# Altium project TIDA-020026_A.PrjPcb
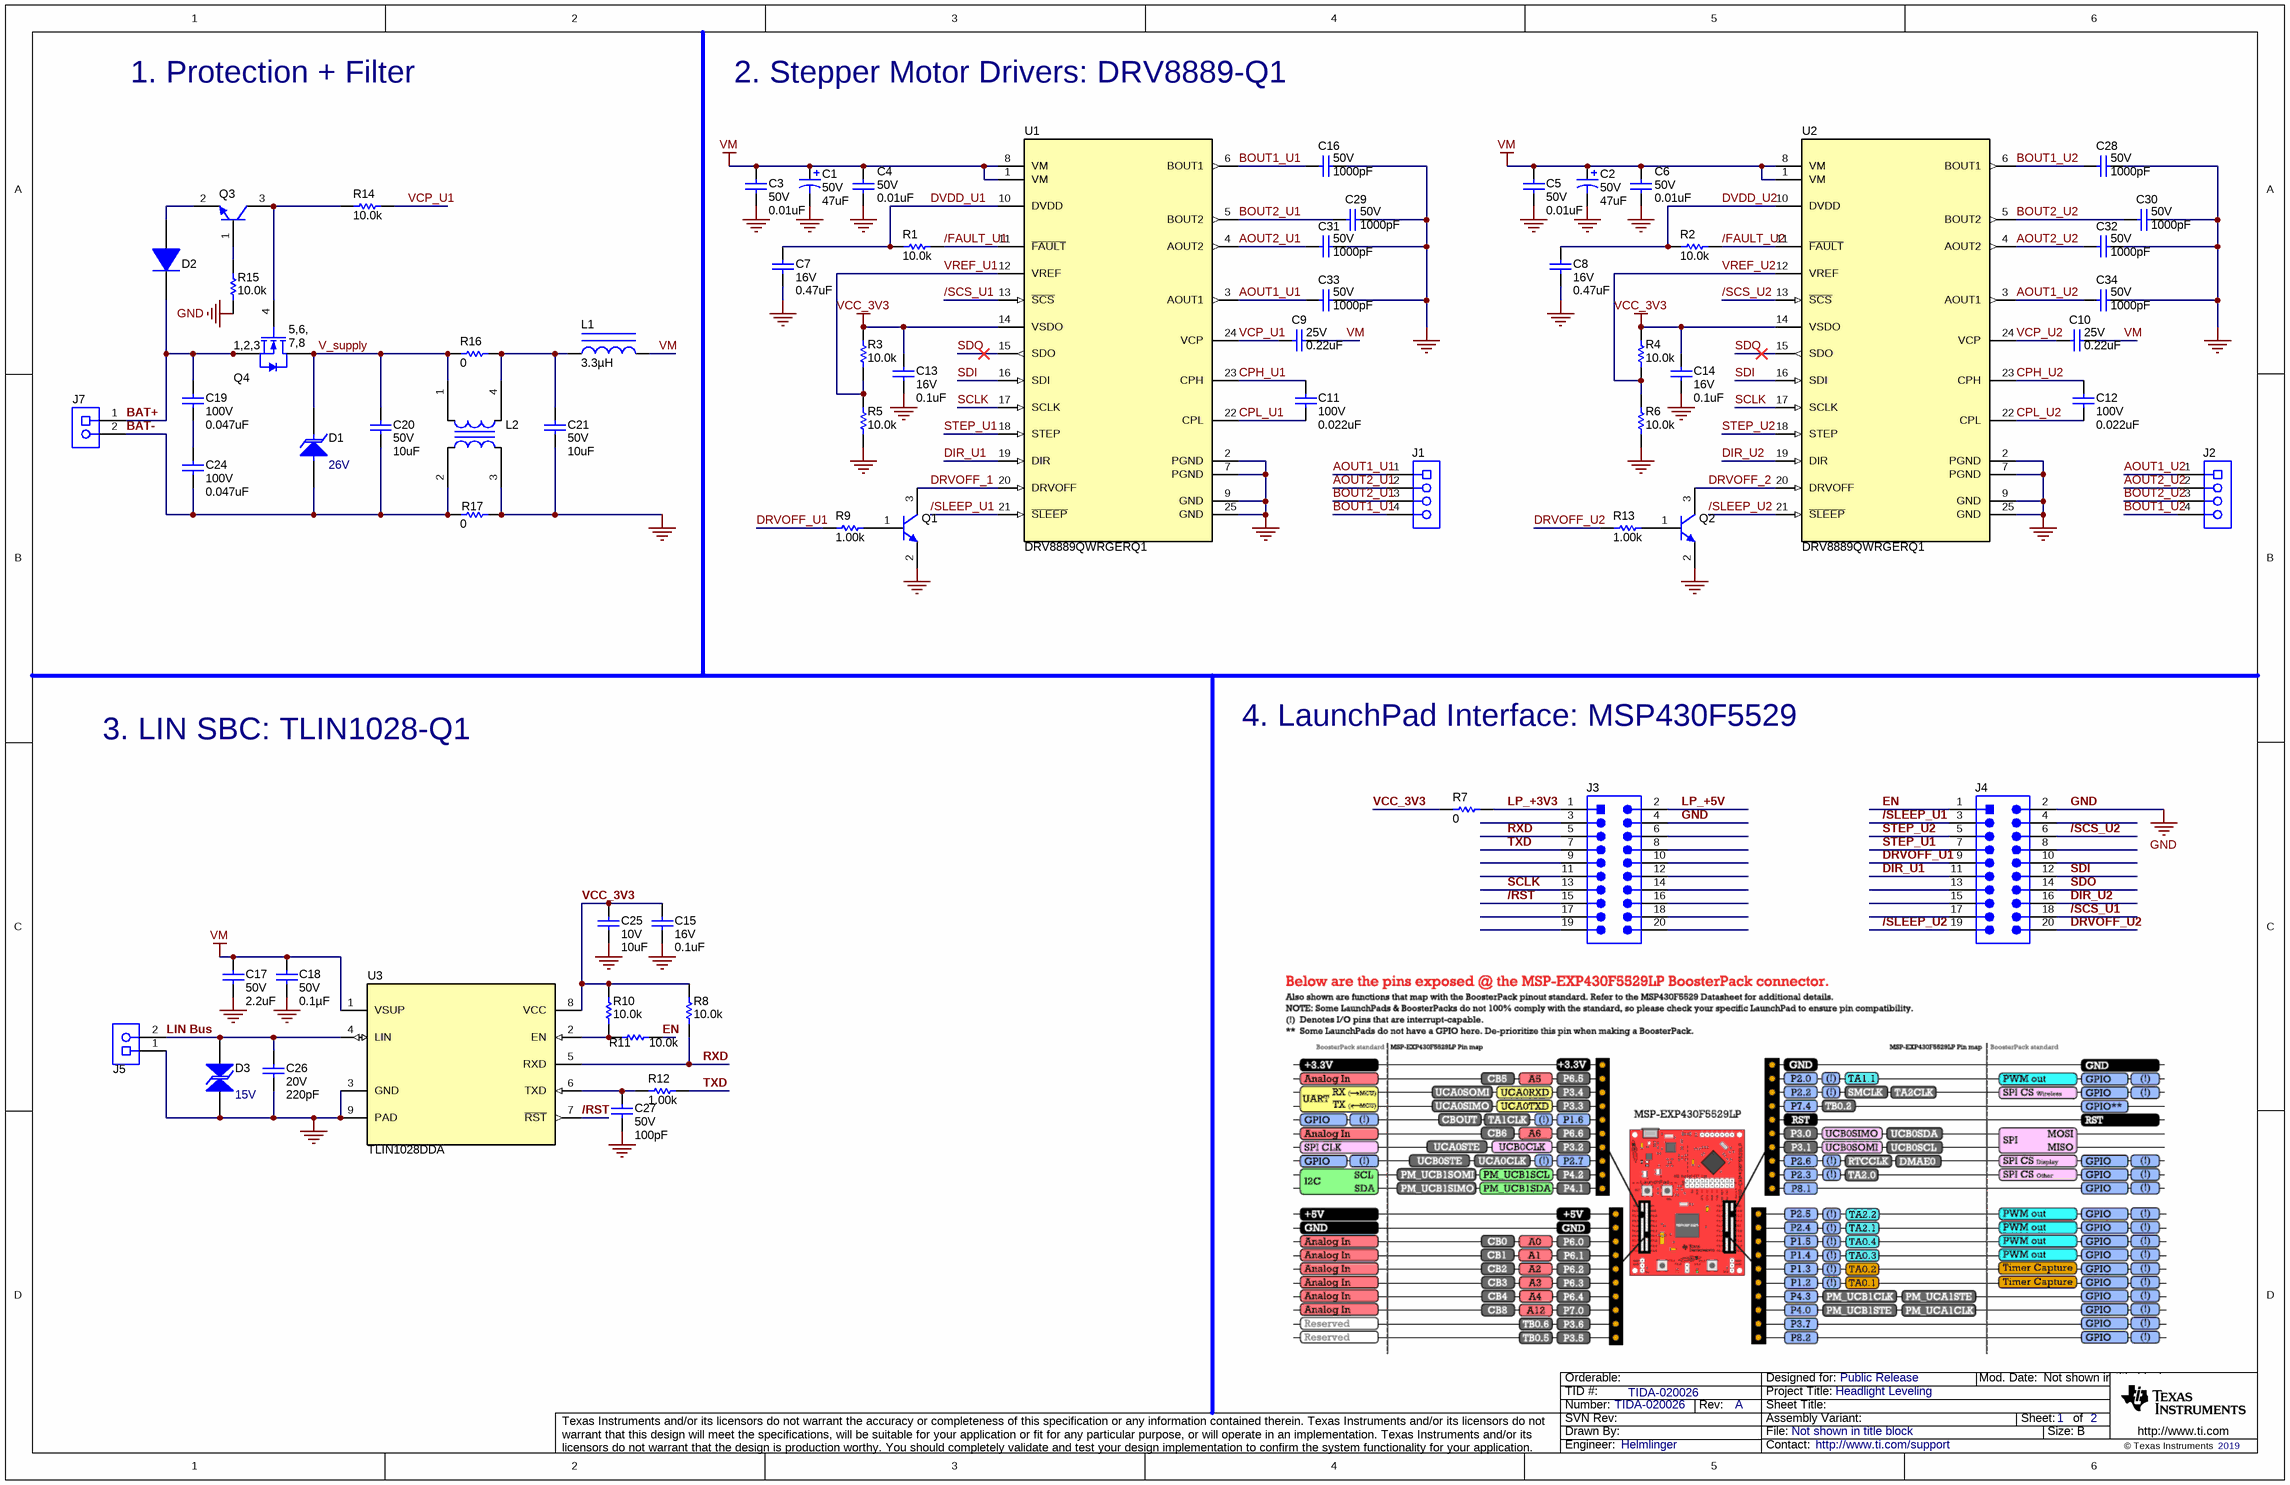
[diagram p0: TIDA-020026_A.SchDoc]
CopyrightYear: 2019; PCB_Layout: Helmlinger; PCB_Rev: A; PRJ_Customer: Public Release; PRJ_Engineer: Helmlinger; PRJ_Number: TIDA-020026; PRJ_Title: Headlight Leveling; SCH_Rev: A; TechSupport: http://www.ti.com/support; TID: TIDA-020026
2 sheets, 76 parts. Net scope: global (net labels, ports and power ports of the same name join across sheets).
Board file: TIDA-020026_A_PCB.PcbDoc
Sheets:
  TIDA-020026_A.SchDoc
  TIDA-020026_A_Hardware.SchDoc

## Sheet TIDA-020026_A.SchDoc
size 431 x 279 mm; Date: Not shown in title block; ApprovedBy: Not shown in title block; CheckedBy: Not shown in title block; Author: Not shown in title block; CompanyName: Not shown in title block; Engineer: Not shown in title block; Organization: Not shown in title block; Address1: Not shown in title block; Address2: Not shown in title block; Address3: Not shown in title block; Address4: Not shown in title block; DocumentNumber: 2; Revision: Use project parameter SCH_Rev; SheetNumber: 1; SheetTotal: 2; PageSetup: Record=PageOptions¦CenterHorizontal=True¦CenterVertical=True¦PrintScale=1.00¦XCorrection=1.00¦YCorrection=1.00¦PrintKind=0¦BorderSize=5000000¦LeftOffset=0¦BottomOffset=0¦Orientation=2¦PaperLength=1000¦PaperWidth=1000¦Scale=100¦PaperSource=15¦PrintQuality=600¦MediaType=1¦DitherType=10¦PaperKind=Letter¦PrintScaleMode=1

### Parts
C1  VDC_V: 50V  ValueDisplayed: 47uF  [Panasonic_D]  (hidden comment: EEEFT1H470AP)
C2  VDC_V: 50V  ValueDisplayed: 47uF  [Panasonic_D]  (hidden comment: EEEFT1H470AP)
C3  VDC_V: 50V  ValueDisplayed: 0.01uF  [0603S]  (hidden comment: GCM188R71H103KA37D)
C4  VDC_V: 50V  ValueDisplayed: 0.01uF  [0603S]  (hidden comment: GCM188R71H103KA37D)
C5  VDC_V: 50V  ValueDisplayed: 0.01uF  [0603S]  (hidden comment: GCM188R71H103KA37D)
C6  VDC_V: 50V  ValueDisplayed: 0.01uF  [0603S]  (hidden comment: GCM188R71H103KA37D)
C7  VDC_V: 16V  ValueDisplayed: 0.47uF  [0603S]  (hidden comment: GCM188R71C474KA55D)
C8  VDC_V: 16V  ValueDisplayed: 0.47uF  [0603S]  (hidden comment: GCM188R71C474KA55D)
C9  VDC_V: 25V  ValueDisplayed: 0.22uF  [0603S]  (hidden comment: GRM188R71E224KA88D)
C10  VDC_V: 25V  ValueDisplayed: 0.22uF  [0603S]  (hidden comment: GRM188R71E224KA88D)
C11  VDC_V: 100V  ValueDisplayed: 0.022uF  [0603S]  (hidden comment: CGA3E2X7R2A223K080AA)
C12  VDC_V: 100V  ValueDisplayed: 0.022uF  [0603S]  (hidden comment: CGA3E2X7R2A223K080AA)
C13  VDC_V: 16V  ValueDisplayed: 0.1uF  [0603S]  (hidden comment: GCM188R71C104KA37J)
C14  VDC_V: 16V  ValueDisplayed: 0.1uF  [0603S]  (hidden comment: GCM188R71C104KA37J)
C15  VDC_V: 16V  ValueDisplayed: 0.1uF  [0603S]  (hidden comment: GCM188R71C104KA37J)
C16  VDC_V: 50V  ValueDisplayed: 1000pF  [0603S]  (hidden comment: C0603C102J5RACAUTO)
C17  VDC_V: 50V  ValueDisplayed: 2.2uF  [0805L]  (hidden comment: UMK212BB7225KG-T)
C18  VDC_V: 50V  ValueDisplayed: 0.1µF  [0603S]  (hidden comment: C0603C104K5RACAUTO)
C19  VDC_V: 100V  ValueDisplayed: 0.047uF  [0603S]  (hidden comment: CGA3E3X7S2A473K080AB)
C20  VDC_V: 50V  ValueDisplayed: 10uF  [1206_180L]  (hidden comment: GRT31CR61H106KE01L)
C21  VDC_V: 50V  ValueDisplayed: 10uF  [1206_180L]  (hidden comment: GRT31CR61H106KE01L)
C24  VDC_V: 100V  ValueDisplayed: 0.047uF  [0603S]  (hidden comment: CGA3E3X7S2A473K080AB)
C25  VDC_V: 10V  ValueDisplayed: 10uF  [0603S]  (hidden comment: GRT188C81A106ME13D)
C26  VDC_V: 20V  ValueDisplayed: 220pF  [0603S]  (hidden comment: CGA3E2C0G1H221J080AA)
C27  VDC_V: 50V  ValueDisplayed: 100pF  [0603S]  (hidden comment: CGA3E2NP01H101J080AA)
C28  VDC_V: 50V  ValueDisplayed: 1000pF  [0603S]  (hidden comment: C0603C102J5RACAUTO)
C29  VDC_V: 50V  ValueDisplayed: 1000pF  [0603S]  (hidden comment: C0603C102J5RACAUTO)
C30  VDC_V: 50V  ValueDisplayed: 1000pF  [0603S]  (hidden comment: C0603C102J5RACAUTO)
C31  VDC_V: 50V  ValueDisplayed: 1000pF  [0603S]  (hidden comment: C0603C102J5RACAUTO)
C32  VDC_V: 50V  ValueDisplayed: 1000pF  [0603S]  (hidden comment: C0603C102J5RACAUTO)
C33  VDC_V: 50V  ValueDisplayed: 1000pF  [0603S]  (hidden comment: C0603C102J5RACAUTO)
C34  VDC_V: 50V  ValueDisplayed: 1000pF  [0603S]  (hidden comment: C0603C102J5RACAUTO)
D1  value 26V  [SMC_265]  (hidden comment: TPSMD26A)
D2  1N4148WS-7-F  [SOD-323]  (value not drawn)
D3  value 15V  [SOD-323-Bi]  (hidden comment: PESD1LIN,115)
J1  1725672  [Phoenix_1725672]  (value not drawn)
J2  1725672  [Phoenix_1725672]  (value not drawn)
J3  PEC10DAAN  [SULLINS_PEC10DAAN]  (value not drawn)
J4  PEC10DAAN  [SULLINS_PEC10DAAN]  (value not drawn)
J5  1727010  [PhoenixConact_1727010]  (value not drawn)
J7  1727010  [PhoenixConact_1727010]  (value not drawn)
L1  ValueDisplayed: 3.3µH  [DFE252012P]  (hidden comment: DFE252012P-3R3M=P2)
L2  ACM70V-701-2PL-TL00  [IND_TDK_ACM7060]  (value not drawn)
Q1  MMBT6429LT1G  [SOT-23]  (value not drawn)
Q2  MMBT6429LT1G  [SOT-23]  (value not drawn)
Q3  MMBTA05LT1G  [SOT-23]  (value not drawn)
Q4  SQ7414AEN-T1-GE3  [PowerPAK_1212-8]  (value not drawn)
R1  ValueDisplayed: 10.0k  [0603S]  (hidden comment: CRCW060310K0FKEA)
R2  ValueDisplayed: 10.0k  [0603S]  (hidden comment: CRCW060310K0FKEA)
R3  ValueDisplayed: 10.0k  [0603S]  (hidden comment: CRCW060310K0FKEA)
R4  ValueDisplayed: 10.0k  [0603S]  (hidden comment: CRCW060310K0FKEA)
R5  ValueDisplayed: 10.0k  [0603S]  (hidden comment: CRCW060310K0FKEA)
R6  ValueDisplayed: 10.0k  [0603S]  (hidden comment: CRCW060310K0FKEA)
R7  ValueDisplayed: 0  [0603S]  (hidden comment: CRCW08050000Z0EA)
R8  ValueDisplayed: 10.0k  [0603S]  (hidden comment: CRCW060310K0FKEA)
R9  ValueDisplayed: 1.00k  [0603S]  (hidden comment: CRCW06031K00FKEA)
R10  ValueDisplayed: 10.0k  [0603S]  (hidden comment: CRCW060310K0FKEA)
R11  ValueDisplayed: 10.0k  [0603S]  (hidden comment: CRCW060310K0FKEA)
R12  ValueDisplayed: 1.00k  [0603S]  (hidden comment: CRCW06031K00FKEA)
R13  ValueDisplayed: 1.00k  [0603S]  (hidden comment: CRCW06031K00FKEA)
R14  ValueDisplayed: 10.0k  [0603S]  (hidden comment: CRCW060310K0FKEA)
R15  ValueDisplayed: 10.0k  [0603S]  (hidden comment: CRCW060310K0FKEA)
R16  ValueDisplayed: 0  [0603S]  (hidden comment: CRCW08050000Z0EA)
R17  ValueDisplayed: 0  [0603S]  (hidden comment: CRCW08050000Z0EA)
U1  DRV8889QWRGERQ1  [RGE0024J]
U2  DRV8889QWRGERQ1  [RGE0024J]
U3  TLIN1028DDA  [DDA0008G_L]

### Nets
GND: C1.2(-) C2.2(-) C3.2 C4.2 C5.2 C6.2 C7.2 C8.2 C13.2 C14.2 C15.2 C16.1 C17.2 C18.2 C21.2 C25.2 C26.2 C27.2 C28.1 C29.1 C30.1 C31.1 C32.1 C33.1 C34.1 D3.1 J3.4 J4.2 J5.1 L2.3 Q1.2(E) Q2.2(E) R5.1 R6.1 R15.1 R17.2 U1.2(PGND) U1.7(PGND) U1.9(GND) U1.25(GND) U2.2(PGND) U2.7(PGND) U2.9(GND) U2.25(GND) U3.3(GND) U3.9(PAD)
VCC_3V3: C13.1 C14.1 C15.1 C25.1 R3.2 R4.2 R7.1 R8.2 R10.2 U1.14(VSDO) U2.14(VSDO) U3.8(VCC)
VM: C1.1(+) C2.1(+) C3.1 C4.1 C5.1 C6.1 C9.1 C10.1 C17.1 C18.1 L1.2 U1.1(VM) U1.8(VM) U2.1(VM) U2.8(VM) U3.1(VSUP)
/FAULT_U1: R1.2 U1.11(~{FAULT})
/FAULT_U2: R2.2 U2.11(~{FAULT})
/RST: J3.15 U3.7(~{RST})
/SCS_U1: J4.18 U1.13(~{SCS})
/SCS_U2: J4.6 U2.13(~{SCS})
/SLEEP_U1: J4.3 U1.21(~{SLEEP})
/SLEEP_U2: J4.19 U2.21(~{SLEEP})
AOUT1_U1: C33.2 J1.1 U1.3(AOUT1)
AOUT1_U2: C34.2 J2.1 U2.3(AOUT1)
AOUT2_U1: C31.2 J1.2 U1.4(AOUT2)
AOUT2_U2: C32.2 J2.2 U2.4(AOUT2)
BAT+: C19.1 D2.1(K) J7.1 Q4.1(S) Q4.2(S) Q4.3(S)
BAT-: C20.2 C24.2 D1.2(A) J7.2 L2.2 R17.1
BOUT1_U1: C16.2 J1.4 U1.6(BOUT1)
BOUT1_U2: C28.2 J2.4 U2.6(BOUT1)
BOUT2_U1: C29.2 J1.3 U1.5(BOUT2)
BOUT2_U2: C30.2 J2.3 U2.5(BOUT2)
CPH_U1: C11.2 U1.23(CPH)
CPH_U2: C12.2 U2.23(CPH)
CPL_U1: C11.1 U1.22(CPL)
CPL_U2: C12.1 U2.22(CPL)
DIR_U1: J4.11 U1.19(DIR)
DIR_U2: J4.16 U2.19(DIR)
DRVOFF_1: Q1.3(C) U1.20(DRVOFF)
DRVOFF_2: Q2.3(C) U2.20(DRVOFF)
DRVOFF_U1: J4.9 R9.1
DRVOFF_U2: J4.20 R13.1
DVDD_U1: C7.1 R1.1 U1.10(DVDD)
DVDD_U2: C8.1 R2.1 U2.10(DVDD)
EN: J4.1 R11.2
LIN Bus: C26.1 D3.2 J5.2 U3.4(LIN)
LP_+3V3: J3.1 R7.2
LP_+5V: J3.2
RXD: J3.5 R8.1 U3.5(RXD)
SCLK: J3.13 U1.17(SCLK) U2.17(SCLK)
SDI: J4.12 U1.16(SDI) U2.16(SDI)
SDO: J4.14 U1.15(SDO) U2.15(SDO)
STEP_U1: J4.7 U1.18(STEP)
STEP_U2: J4.5 U2.18(STEP)
TXD: J3.7 R12.2
V_supply: C20.1 D1.1(K) L2.1 Q4.5(D) Q4.6(D) Q4.7(D) Q4.8(D) Q4.9(D) R16.1
VCP_U1: C9.2 R14.2 U1.24(VCP)
VCP_U2: C10.2 U2.24(VCP)
VREF_U1: R3.1 R5.2 U1.12(VREF)
VREF_U2: R4.1 R6.2 U2.12(VREF)
NetC19_2: C19.2 C24.1
NetC21_1: C21.1 L1.1 L2.4 R16.2
NetC27_1: C27.1 R12.1 U3.6(TXD)
NetD2_2: D2.2(A) Q3.2(E)
NetQ1_1: Q1.1(B) R9.2
NetQ2_1: Q2.1(B) R13.2
NetQ3_1: Q3.1(B) R15.2
NetQ3_3: Q3.3(C) Q4.4(G) R14.1
NetR10_1: R10.1 R11.1 U3.2(EN)

Not connected (* = marked no-connect by the designer): J3 3 6 8 9 10 11 12 14 16 17 18 19 20; J4 4 8 10 13 15 17

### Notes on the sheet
- 1. Protection + Filter
- 2. Stepper Motor Drivers: DRV8889-Q1
- 3. LIN SBC: TLIN1028-Q1
- 4. LaunchPad Interface: MSP430F5529
- (near J3) R7: optional
  will be populated if external supply is needed.

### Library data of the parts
C1 C2 = CMP-0011204-2: CAP, AL, 47 uF, 50 V, +/- 20%, 0.68 ohm, AEC-Q200 Grade 2, SMD; Manufacturer: Panasonic; TaMin_C: -55°C; ESR_ohm: 0.68; Polarized: Y; SizeAreaWB_mm2: 73.96; U/M: EA; Value: 47uF; TaMax_C: 105°C; SizeZ_mm: 6.1; SizeX_mm: 6.6; Cap_Case: 6.3x5.8mm; SizeArea_mm2: 43.56; CompType: Capacitor; Cap_F: 47µF; IRMS_A: 195mA; AEC Grade: 2; AEC Category: Q200
C3-C6 = CMP-0007143-4: CAP, CERM, 0.01 uF, 50 V, +/- 10%, X7R, AEC-Q200 Grade 1, 0603; Manufacturer: MuRata; TaMin_C: -55°C; Polarized: N; SizeAreaWB_mm2: 4.68; Value1: Unknown; U/M: EA; Value: 0.01uF; TaMax_C: 125°C; SizeZ_mm: 1; SizeX_mm: 1.6; SizeY_mm: 0.8; Cap_Case: 0603; SizeArea_mm2: 1.28; AEC Qualified: Y; Cap_F: 10nF; AEC Category: Q200
C7 C8 = CMP-0007138-4: CAP, CERM, 0.47 uF, 16 V, +/- 10%, X7R, AEC-Q200 Grade 1, 0603; Manufacturer: MuRata; TaMin_C: -55°C; Polarized: N; SizeAreaWB_mm2: 4.68; Value1: Unknown; U/M: EA; Value: 0.47uF; TaMax_C: 125°C; SizeZ_mm: 1; SizeX_mm: 1.6; SizeY_mm: 0.8; Cap_Case: 0603; SizeArea_mm2: 1.28; AEC Qualified: Y; Cap_F: 470nF; AEC Category: Q200
C9 C10 = CMP-0007415-4: CAP, CERM, 0.22 uF, 25 V, +/- 10%, X7R, 0603; Manufacturer: MuRata; TaMin_C: -55°C; Polarized: N; SizeAreaWB_mm2: 4.68; Value1: Unknown; U/M: EA; Value: 0.22uF; TaMax_C: 125°C; SizeZ_mm: 1; SizeX_mm: 1.6; SizeY_mm: 0.8; Cap_Case: 0603; SizeArea_mm2: 1.28; Cap_F: 220nF; AEC Category: Q200
C11 C12 = CMP-0007086-4: CAP, CERM, 0.022 uF, 100 V, +/- 10%, X7R, AEC-Q200 Grade 1, 0603; Manufacturer: TDK; TaMin_C: -55°C; ESR_ohm: 0.083542; Polarized: N; SizeAreaWB_mm2: 4.68; Value1: 0.083542 ohm; U/M: EA; TaMax_C: 125°C; SizeZ_mm: 1; SizeX_mm: 1.6; SizeY_mm: 0.8; Cap_Case: 0603; SizeArea_mm2: 1.28; AEC Qualified: Y; Cap_F: 22nF; IRMS_A: 609.312mA; AEC Category: Q200
C13-C15 = CMP-0007135-4: CAP, CERM, 0.1 uF, 16 V, +/- 10%, X7R, AEC-Q200 Grade 1, 0603; Manufacturer: MuRata; TaMin_C: -55°C; Polarized: N; SizeAreaWB_mm2: 4.68; Value1: Unknown; U/M: EA; Value: 0.1uF; TaMax_C: 125°C; SizeZ_mm: 1; SizeX_mm: 1.6; SizeY_mm: 0.8; Cap_Case: 0603; SizeArea_mm2: 1.28; AEC Qualified: Y; Cap_F: 100nF; AEC Category: Q200
C16 C28-C34 = CMP-0006844-4: CAP, CERM, 1000 pF, 50 V, +/- 5%, X7R, AEC-Q200 Grade 1, 0603; Manufacturer: Kemet; TaMin_C: -55°C; Polarized: N; SizeAreaWB_mm2: 4.68; Value1: Unknown; U/M: EA; Value: 1000pF; TaMax_C: 125°C; SizeZ_mm: 1; SizeX_mm: 1.6; SizeY_mm: 0.8; Cap_Case: 0603; SizeArea_mm2: 1.28; AEC Qualified: Y; Cap_F: 1nF; AEC Category: Q200
C17 = CMP-0008425-2: CAP, CERM, 2.2 uF, 50 V, +/- 10%, X7R, 0805; Manufacturer: Taiyo Yuden; TaMin_C: -55°C; Polarized: N; SizeAreaWB_mm2: 6.75; Value1: Unknown; U/M: EA; Value: 2.2uF; TaMax_C: 125°C; SizeZ_mm: 1.45; SizeX_mm: 2; SizeY_mm: 1.25; Cap_Case: 0805; SizeArea_mm2: 2.5; Cap_F: 2.2µF; AEC Category: Q200
C18 = CMP-0079602-1: CAP, CERM, 0.1 µF, 50 V,+/- 10%, X7R, AEC-Q200 Grade 1, 0603; Manufacturer: Kemet; TaMin_C: -55°C; Polarized: N; SizeAreaWB_mm2: 4.68; U/M: EA; Value: 0.1uF; TaMax_C: 125°C; SizeZ_mm: 1; SizeX_mm: 1.6; SizeY_mm: 0.8; Cap_Case: 0603; SizeArea_mm2: 1.28; AEC Qualified: Y; Cap_F: 100nF; AEC Category: Q200
C19 C24 = CMP-0007101-4: CAP, CERM, 0.047 uF, 100 V, +/- 10%, X7S, AEC-Q200 Grade 1, 0603; Manufacturer: TDK; TaMin_C: -55°C; ESR_ohm: 0.089796; Polarized: N; SizeAreaWB_mm2: 4.68; Value1: 0.089796 ohm; U/M: EA; TaMax_C: 125°C; SizeZ_mm: 1; SizeX_mm: 1.6; SizeY_mm: 0.8; Cap_Case: 0603; SizeArea_mm2: 1.28; AEC Qualified: Y; Cap_F: 47nF; IRMS_A: 567.484mA; AEC Category: Q200
C20 C21 = CMP-0009015-2: CAP, CERM, 10 uF, 50 V, +/- 10%, X5R, AEC-Q200 Grade 1, 1206; Manufacturer: MuRata; TaMin_C: -55°C; Polarized: N; SizeAreaWB_mm2: 10.92; Value1: Unknown; U/M: EA; Value: 10uF; TaMax_C: 85°C; SizeZ_mm: 1.8; SizeX_mm: 3.2; SizeY_mm: 1.6; Cap_Case: 1206; SizeArea_mm2: 5.12; AEC Qualified: Y; Cap_F: 10µF; AEC Grade: 1; AEC Category: Q200
C25 = CMP-0007500-4: CAP, CERM, 10 uF, 10 V, +/- 20%, X6S, AEC-Q200 Grade 2, 0603; Manufacturer: MuRata; TaMin_C: -55°C; Polarized: N; SizeAreaWB_mm2: 4.68; Value1: Unknown; U/M: EA; Value: 10uF; TaMax_C: 105°C; SizeZ_mm: 1; SizeX_mm: 1.6; SizeY_mm: 0.8; Cap_Case: 0603; SizeArea_mm2: 1.28; AEC Qualified: Y; Cap_F: 10µF; AEC Grade: 2; AEC Category: Q200
C26 = CMP-0007072-1: CAP, CERM, 220 pF, 20 V, +/- 5%, C0G/NP0, AEC-Q200 Grade 1, 0603; Manufacturer: TDK; TaMin_C: -55°C; Polarized: N; SizeAreaWB_mm2: 4.68; Value1: Unknown; U/M: EA; Value: 220pF; TaMax_C: 125°C; SizeZ_mm: 1; SizeX_mm: 1.6; SizeY_mm: 0.8; Cap_Case: 0603; SizeArea_mm2: 1.28; AEC Qualified: Y; AEC Category: Q200
C27 = CMP-0007075-4: CAP, CERM, 100 pF, 50 V, +/- 5%, C0G/NP0, AEC-Q200 Grade 0, 0603; Manufacturer: TDK; TaMin_C: -55°C; Polarized: N; SizeAreaWB_mm2: 4.68; Value1: Unknown; U/M: EA; Value: 100pF; TaMax_C: 150°C; SizeZ_mm: 1; SizeX_mm: 1.6; SizeY_mm: 0.8; Cap_Case: 0603; SizeArea_mm2: 1.28; AEC Qualified: Y; AEC Grade: 0; AEC Category: Q200
D1 = CMP-0005729-4: Diode, TVS, Uni, 26 V, 42.1 Vc, AEC-Q101, SMC; Manufacturer: Littelfuse; Vc: 42.1V; Value1: 3000W; Ipp: 71.3A; SizeAreaWB_mm2: 78.5757; AEC Category: Q101; AEC Qualified: Y; SizeArea_mm2: 46.8857; SizeZ_mm: 2.62; Vbr_Max: 31.9V; RJA_CperW: 75; Vbr_Min: 28.9V; Ppk: 3kW; SizeY_mm: 5.905; SizeX_mm: 7.94
D2 = CMP-0079597-2: Diode, Switching, 75 V, 0.15 A, AEC-Q101, SOD-323; Manufacturer: Diodes Inc.; Value: 75V; Vf_V: 1.25V; Value1: 0.15A; Io_A: 150mA; TJmax_C: 150°C; AEC Category: Q101; AEC Qualified: Y; SizeArea_mm2: 3.645; SizeAreaWB_mm2: 8.695; SizeX_mm: 2.7; SizeY_mm: 1.35; SizeZ_mm: 1
D3 = CMP-0005821-3: Diode, TVS, Bi, 15 V, SOD-323; Manufacturer: NXP Semiconductor; SizeAreaWB_mm2: 8.695; Ppk: 160W; SizeZ_mm: 1; SizeY_mm: 1.35; SizeArea_mm2: 3.645; SizeX_mm: 2.7; AEC Category: Q101
J1 J2 = CMP-0055518-1: Terminal Block, 4x1, 2.54 mm, Green, TH; Manufacturer: Phoenix Contact; CNHeader: FALSE; Current_A: 6A; Gender: Female; Cert_CSA: Y; Voltage_V: 125V; Row_Count: 1; Pitch_mm: 2.54; CT: TRUE
J3 J4 = CMP-0054623-2: Header, 2.54mm, 10x2, Tin, TH; Manufacturer: Sullins Connector Solutions; Current_A: 3A; Green_Lifecycle: Not Set; Shrouded: N; Gender: Male; Green_REACh: Incomplete; Row_Count: 2; RowSpacing_mm: 2.54; Cert_UL: Y
J5 J7 = CMP-0055472-1: Conn Term Block, 2POS, 3.81mm, TH; Manufacturer: Phoenix Contact; CT: TRUE; Green_REACh: Incomplete; CompType: Terminal Block; CNHeader: FALSE; Green_Lifecycle: Not Set
L1 = CMP-0082610-1: Inductor, Shielded, Metal Composite, 3.3 µH, 1.7 A, 0.14 ohm, SMD; Manufacturer: MuRata; Isat: 2.3A @ 30% inductance drop; Irms: 1.7A @ 40C rise; SizeAreaWB_mm2: 10.5; DCR_ohm: 0.14; Value: 3.3uH; Imax_A: 1.7A; SizeZ_mm: 1.2; SizeX_mm: 2.5; SizeY_mm: 2; SizeArea_mm2: 5; AEC Qualified: N; AEC Category: Q200
L2 = CMP-0085405-1: Coupled inductor, 0.015 ohm, AEC-Q200 Grade 1, SMD; Manufacturer: TDK; DCR_ohm: 0.015; AEC Qualified: Y; AEC Category: Q200; AEC Grade: 1
Q1 Q2 = CMP-0078179-2: Transistor, NPN, 45 V, 0.2 A, AEC-Q101, SOT-23; Manufacturer: ON Semiconductor; SizeZ_mm: 1.1; Value2: 1250; SizeArea_mm2: 7.5; Value: 45 V; Green_REACh: Passed; Vcesat1_V: 200mV; SizeAreaWB_mm2: 14; Vceo_V: 45V; AEC Qualified: Y; CompType: BJT; PNP: 0; TaMax_C: 150°C; Green_Lifecycle: Active; TaMin_C: -55°C; Value1: 0.2 A; NPN: 1; SizeY_mm: 3; IcRated_A: 200mA; AEC Category: Q101; SizeX_mm: 2.5
Q3 = CMP-0000488-2: Transistor, NPN, 60 V, 0.5 A, AEC-Q101, SOT-23; Manufacturer: ON Semiconductor; TaMax_C: 150°C; Value1: 0.5 A; Vcesat1_V: 250mV; SizeX_mm: 2.5; SizeY_mm: 3; TaMin_C: -55°C; IcRated_A: 500mA; CompType: BJT; SizeZ_mm: 1.1; AEC Qualified: Y; Value: 60 V; SizeArea_mm2: 7.5; NPN: 1; Vceo_V: 60V; PNP: 0; AEC Category: Q101; SizeAreaWB_mm2: 14; U/M: EA
Q4 = CMP-0000873-2: MOSFET, N-CH, 60 V, 16 A, AEC-Q101, PowerPAK 1212; Alternate Manufacturer: None; Manufacturer: Vishay-Siliconix; SizeZ_mm: 1.04; ChType: N; Value2: 16 nC; Value1: 0.03; VdsMax_V: 60V; SizeX_mm: 3.3; Vgs_V: 20V; AEC Qualified: Y; Value: 60V; Rdson45_ohm: 0.036; SizeArea_mm2: 10.89; AEC Category: Q101; IdsMax_A: 16A; SizeAreaWB_mm2: 18.49; U/M: EA; QgTyp_nC: 16
R1-R6 R8 R10 R11 R14 R15 = CMP-0021998-4: RES, 10.0 k, 1%, 0.1 W, AEC-Q200 Grade 0, 0603; Manufacturer: Vishay-Dale; Power_W: 100mW; TempCo: 100 ppm/C; Value_Code: 10k0; Value: 10.0k; EIA_Code: E96; Res_ohm: 10k; SizeX_mm: 1.6; SizeY_mm: 0.8; SizeZ_mm: 1; Value2: 0.1W; SizeArea_mm2: 1.28; AEC Qualified: Y; VDC_V: 75V; AEC Category: Q200; AEC Grade: 0
R7 R16 R17 = CMP-0025697-4: RES, 0, 5%, 0.1 W, AEC-Q200 Grade 0, 0603; Manufacturer: Vishay-Dale; PartNumber: CRCW06030000Z0EA; Power_W: 100mW; TempCo: 200 ppm/C; Value_Code: 0000; Value: 0; EIA_Code: E24; SizeX_mm: 1.6; SizeY_mm: 0.8; SizeZ_mm: 1; Value2: 0.1W; SizeArea_mm2: 1.28; AEC Qualified: Y; VDC_V: 75V; AEC Category: Q200
R9 R12 R13 = CMP-0022109-5: RES, 1.00 k, 1%, 0.1 W, AEC-Q200 Grade 0, 0603; Manufacturer: Vishay-Dale; Power_W: 100mW; TempCo: 100 ppm/C; Value_Code: 1k00; Value: 1.00k; EIA_Code: E96; Res_ohm: 1k; SizeX_mm: 1.6; SizeY_mm: 0.8; SizeZ_mm: 1; Value2: 0.1W; SizeArea_mm2: 1.28; AEC Qualified: Y; VDC_V: 75V; AEC Category: Q200; AEC Grade: 0
U1 U2 = CMP-0084889-1: Automotive Stepper Driver With Integrated Current Sense, 1/32 Microstepping, and Stall Detection, RGE0024J (VQFN-24); Alternate Manufacturer: Texas Instruments; SizeX_mm: 4; CompType: IC; AEC Category: Q200; SizeZ_mm: 1; AEC Qualified: Y; SizeArea_mm2: 16; SizeAreaWB_mm2: 25
U3 = CMP-0074642-4: Automotive Local Interconnect Network Transceiver, DDA0008G (SOIC-8); Manufacturer: Texas Instruments; SizeZ_mm: 1.7; SizeX_mm: 5.99; SizeY_mm: 4.89; SizeArea_mm2: 29.2911; CompType: IC; U/M: EA; SizeAreaWB_mm2: 55.0511; AEC Category: Q200; AEC Qualified: N

## Sheet TIDA-020026_A_Hardware.SchDoc
size 431 x 279 mm; Date: Not shown in title block; ApprovedBy: Not shown in title block; CheckedBy: Not shown in title block; Author: Not shown in title block; CompanyName: Not shown in title block; Engineer: Not shown in title block; Organization: Not shown in title block; Address1: Not shown in title block; Address2: Not shown in title block; Address3: Not shown in title block; Address4: Not shown in title block; DocumentNumber: 3; Revision: Use project parameter SCH_Rev; SheetNumber: 3; SheetTotal: 3; PageSetup: Record=PageOptions¦CenterHorizontal=True¦CenterVertical=True¦PrintScale=1.00¦XCorrection=1.00¦YCorrection=1.00¦PrintKind=0¦BorderSize=5000000¦LeftOffset=0¦BottomOffset=0¦Orientation=2¦PaperLength=1000¦PaperWidth=1000¦Scale=100¦PaperSource=15¦PrintQuality=600¦MediaType=1¦DitherType=10¦PaperKind=Letter¦PrintScaleMode=1
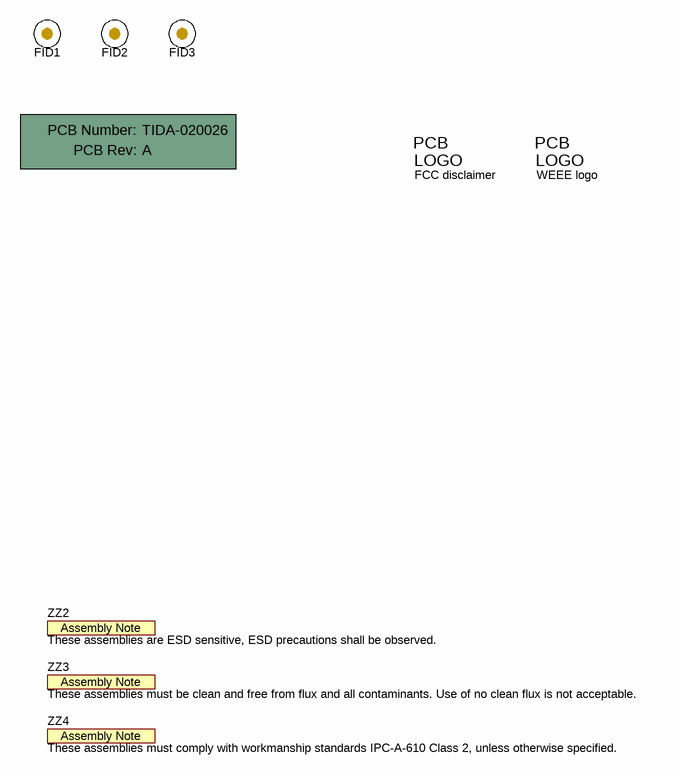
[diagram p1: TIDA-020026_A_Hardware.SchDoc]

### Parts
!PCB  Printed Circuit Board  (value not drawn)  (mechanical)
FID1  Fiducial  [Fiducial10-20]  (value not drawn)
FID2  Fiducial  [Fiducial10-20]  (value not drawn)
FID3  Fiducial  [Fiducial10-20]  (value not drawn)
Logo3  FCC disclaimer  [FCC_disclaimer]  (no BOM)
Logo4  WEEE logo  [WEEE_Minimum]  (no BOM)
ZZ2  These assemblies are ESD sensitive, ESD precautions shall be observed.  [AssemblyNote]  (no BOM)
ZZ3  These assemblies must be clean and free from flux and all contaminants. Use of no clean flux is not acceptable.  [AssemblyNote]  (no BOM)
ZZ4  These assemblies must comply with workmanship standards IPC-A-610 Class 2, unless otherwise specified.  [AssemblyNote]  (no BOM)

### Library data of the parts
!PCB = CMP-0003618-2: Manufacturer: Any; PartNumber: TIDA-020026
FID1-FID3 = CMP-0077181-1: Fiducial mark.  There is nothing to buy or mount.
Logo3 = CMP-0074847-1: FCC_disclaimer; Library Reference: Logo
Logo4 = CMP-0074769-1
ZZ2 = CMP-0077236-1
ZZ3 = CMP-0077237-1
ZZ4 = CMP-0077238-1

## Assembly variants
001: not fitted FID1 FID2 FID3 R11 R16 R17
